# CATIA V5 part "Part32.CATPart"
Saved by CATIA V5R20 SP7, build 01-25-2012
Part number: corps vérin droit
Bounding box of the stored display mesh (mm): x -22.68 to 6.616, y -59 to -0.033, z -12.425 to -1.393
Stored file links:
  F:\Travaux\Modélisations\CFAO_2011\CFAO_2011_MMS\CFAO_2011_MMS_DONE\CFAO_2011_MMS_jboiteux\Catia\Part32.CATPart
  U:\finthinkmotion\stepper.CATProduct
  F:\Travaux\Modélisations\CFAO_2011\CFAO_2011_MMS\CFAO_2011_MMS_DONE\CFAO_2011_MMS_jboiteux\Catia\bati.CATPart
  F:\Travaux\Modélisations\CFAO_2011\CFAO_2011_MMS\CFAO_2011_MMS_DONE\CFAO_2011_MMS_jboiteux\Catia\Part1.CATPart
  F:\Travaux\Modélisations\CFAO_2011\CFAO_2011_MMS\CFAO_2011_MMS_DONE\CFAO_2011_MMS_jboiteux\Catia\part3.CATPart
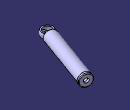
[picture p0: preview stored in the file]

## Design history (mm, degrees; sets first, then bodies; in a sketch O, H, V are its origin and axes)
Parameters
  rayontube = 9 mm {= External.royontubebati}
  `longueur pied` = 108 mm {= External.longueurpied}
External parameters (linked from other documents)
  External.royontubebati = 9 mm
  External.longueurpied = 108 mm
Set1
  Plane1: linked copy from another document
  Point1: linked copy from another document
  Plane2: linked copy from another document
  Line1: linked copy from another document
  Point2: linked copy from another document
  Line2: linked copy from another document
Body1 (main body)
  Plane3: type Offset, RefPlane Plane1, Offset 2 {= rayontube /4.5}
  Plane4: type Offset, RefPlane Plane1, Offset 2, reversed
  Sketch1 on Plane1, origin (0, 0, -7.6), H (1, 0, 0), V (0, 1, 0)
    arc A1 centre (-17.69, -54) radius 5 from (-17.69, -59) to (-17.69, -49) ccw
    point P1 (-17.69, -54)
    reference projected point E1 (-17.69, -54) from Point1
    arc A2 centre (-17.69, -54) radius 4 from (-17.69, -58) to (-17.69, -50) ccw
    line L1 (-17.69, -59) -> (-17.69, -58)
    point P3 (-17.69, -49)
    point P4 (-17.69, -50)
    line L2 (-17.69, -49) -> (-17.69, -50)
    radius A2 = 4 {= rayontube *2/2/3+1mm}
    radius A1 = 5 {= rayontube *2/2/3+2mm}
    coincidence: E1 P1, L1 P1, L1 P3, L1 P4
    vertical: L1 V, L2 V
  Shaft1: profile Sketch1, axis Sketch1.L1, angle 360
  Split1: SplitPlane Plane4
  Split2: SplitPlane Plane3
  Point3: type OnCurve, Support Line1, Ratio 0
  Plane5: type OffsetPt, RefPlane Plane2, RefPoint Point3
  Sketch2 on Plane5, origin (31.1846, -72.0488, -26.1922), H (0.9094, -0.3384, -0.2418), V (0.2184, -0.1063, 0.9701)
    circle A1 centre (-55.0503, 5.4428) radius 4.95
    point P1 (-55.0503, 5.4428)
    reference projected point E1 (-55.0503, 5.4428) from Point2
    radius A1 = 4.95 {= rayontube *1.1/2}
    coincidence: E1 P1
  Pad1: profile Sketch2, direction (-0.354, -0.935, -0.0228), length -4.0909 {= -rayontube /2.2}, opposite side length 54 {= `longueur pied` /2}
  Sketch3 on start face of Pad1, origin (55.4453, -23.5373, -23.7683), H (-0.9094, 0.3384, 0.2418), V (0.2184, -0.1063, 0.9701)
    circle A1 centre (60.1119, 2.9524) radius 3.95
    point P1 (60.1119, 2.9524)
    reference projected point E1 (60.1119, 2.9524) from Point2
    radius A1 = 3.95 {= rayontube *79/180}
    coincidence: E1 P1
  Pocket1: profile Sketch3, direction (-0.354, -0.935, -0.0228), length 48.5 {= `longueur pied` /2-rayontube/2-1mm}
  Fillet1: radius 1 {= rayontube /9}, on edge [face of Pad1 from Sketch2.A1 | end face of Pad1]
  Sketch4 on start face of Pad1, origin (55.4453, -23.5373, -23.7683), H (-0.9094, 0.3384, 0.2418), V (0.2184, -0.1063, 0.9701)
    projected circle E1 centre (60.1119, 2.9524) radius 4.95 from edge [start face of Pad1 | face of Pad1 from Sketch2.A1]
    circle A1 centre (60.1119, 2.9524) radius 1.8
    point P1 (60.1119, 2.9524)
    reference projected point E2 (60.1119, 2.9524) from Line2
    radius A1 = 1.8 {= rayontube *0.4/2}
    coincidence: E2 P1
  Pad2: profile Sketch4, direction (0.354, 0.935, 0.0228), length 2
  Fillet2: radius 0.5 {= rayontube /18}, on edge [face of Pad2 from Sketch4.E1 | end face of Pad2]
